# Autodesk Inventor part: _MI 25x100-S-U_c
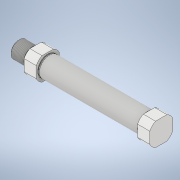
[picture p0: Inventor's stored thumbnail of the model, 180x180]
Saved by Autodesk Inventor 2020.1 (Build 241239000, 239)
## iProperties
Created: 2020-04
Part Number: _MI 25x100-S-U_c
Material: Generic
Document SubType Name: Modeling
Designer: Safarabadi
Density: 1 g/cm^3
Appearance: Default
Author: Safarabadi
Revision Number: NONE
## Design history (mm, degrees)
feature "_MI 25x100-S-U_c"
thread "Thread1" dims "d0" = 16.68, "d1" = 0
body "Solid1"
